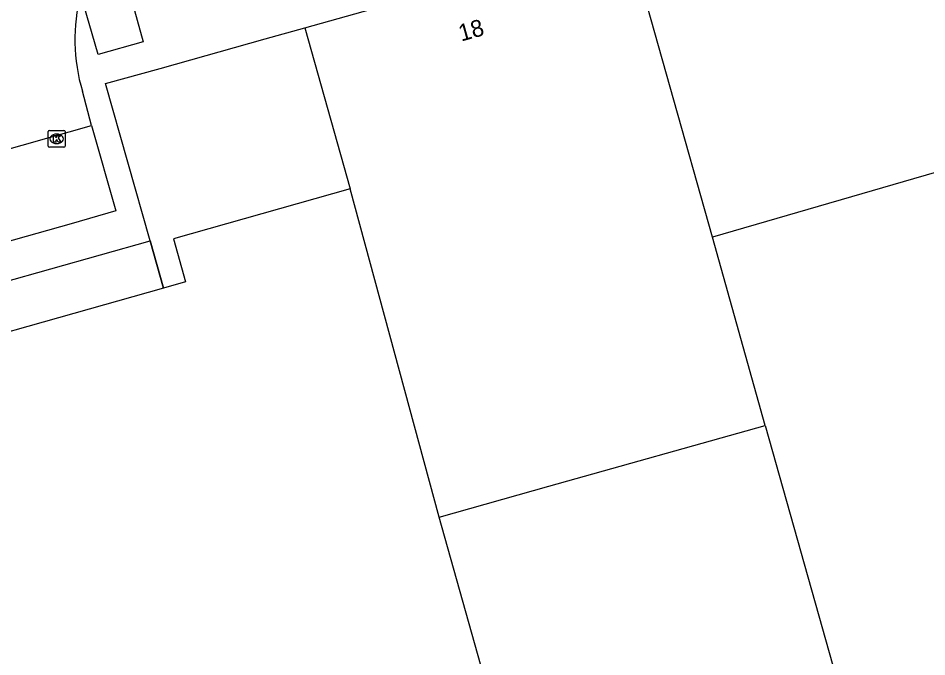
# Model space of a CAD drawing. Extents: x 159689 to 160786, y 387323 to 388339.
# Drawn here: x 159968.5 to 160022.4, y 388098.5 to 388136.4 of the extents above; entities that cross this region are included whole.
import ezdxf

# ---------------------------------------------------------------- set-up
doc = ezdxf.new("R2010")
doc.units = 0
for name, color, linetype in [('IMGEO_Hek', 7, 'Continuous'), ('IMGEO_Kolk', 7, 'Continuous'), ('IMGEO_Pand', 7, 'Continuous'), ('IMGEO_Pand_nummerreeks', 7, 'Continuous'), ('IMGEO_Rijbaan_lokaal_gesloten', 7, 'Continuous'), ('IMGEO_Voetpad_open', 7, 'Continuous')]:
    doc.layers.add(name, color=color, linetype=linetype)

msp = doc.modelspace()

# ---------------------------------------------------------------- linework, layer by layer
at = {"layer": 'IMGEO_Hek'}
msp.add_lwpolyline([(159976.338, 388123.222), (159977.127, 388120.422)], dxfattribs=at)
at = {"layer": 'IMGEO_Kolk'}
for p, q in [((159970.298, 388128.856), (159970.298, 388129.708)), ((159970.373, 388129.782), (159971.225, 388129.782)), ((159970.786, 388129.562), (159970.811, 388129.562)), ((159971.299, 388129.708), (159971.299, 388128.856)), ((159970.809, 388129.002), (159970.784, 388129.002)), ((159971.225, 388128.782), (159970.373, 388128.782))]:
    msp.add_line(p, q, dxfattribs=at)
for points in [[(159970.298, 388128.856), (159970.298, 388129.708)], [(159970.373, 388129.782), (159971.225, 388129.782)], [(159970.619, 388129.482), (159970.742, 388129.482), (159970.742, 388129.331), (159970.872, 388129.482), (159971.036, 388129.482), (159970.89, 388129.331), (159971.043, 388129.082), (159970.891, 388129.082), (159970.806, 388129.246), (159970.742, 388129.179), (159970.742, 388129.082), (159970.619, 388129.082), (159970.619, 388129.482)], [(159971.299, 388129.708), (159971.299, 388128.856)], [(159971.225, 388128.782), (159970.373, 388128.782)]]:
    msp.add_lwpolyline(points, dxfattribs=at)
for centre, start, end in [((159970.375, 388129.706), 91.552, 178.448), ((159970.375, 388129.706), 91.552, 178.448), ((159971.223, 388129.706), 1.552, 88.448), ((159971.223, 388129.706), 1.552, 88.448), ((159970.375, 388128.858), 181.552, 268.448), ((159970.375, 388128.858), 181.552, 268.448), ((159971.223, 388128.858), 271.552, 358.448), ((159971.223, 388128.858), 271.552, 358.448)]:
    msp.add_arc(centre, 0.0765, start, end, dxfattribs=at)
for centre, major_axis, ratio, start_param, end_param in [((159970.785, 388129.282), (-0.387, 0.002), 0.722429, 4.712389, 7.853982), ((159970.81, 388129.282), (-0.39, 0.002), 0.717154, 1.570796, 4.712389)]:
    msp.add_ellipse(centre, major_axis=major_axis, ratio=ratio, start_param=start_param, end_param=end_param, dxfattribs=at)
at = {"layer": 'IMGEO_Pand'}
for points in [[(159985.526, 388135.869), (160000, 388139.941), (160004.68, 388141.258)], [(160009.691, 388123.443), (160004.68, 388141.258)], [(159985.526, 388135.869), (159988.214, 388126.311)], [(160048.204, 388134.628), (160009.691, 388123.443)], [(159988.214, 388126.311), (159977.726, 388123.346), (159978.446, 388120.795), (159977.127, 388120.422)], [(159993.49, 388106.837), (159988.214, 388126.311)], [(160012.83, 388112.278), (160009.691, 388123.443)], [(159977.127, 388120.422), (159959.347, 388115.395), (159959.027, 388116.529), (159954.546, 388115.888), (159954.734, 388115.225), (159953.294, 388114.818), (159953.106, 388115.482), (159948.902, 388113.675), (159949.225, 388112.529), (159934.794, 388108.418)], [(159993.49, 388106.837), (160000, 388108.668), (160012.83, 388112.278)], [(160012.83, 388112.278), (160019.582, 388088.279)], [(160000.247, 388082.819), (160000, 388083.697), (159993.49, 388106.837)]]:
    msp.add_lwpolyline(points, dxfattribs=at)
at = {"layer": 'IMGEO_Rijbaan_lokaal_gesloten'}
for points in [[(159972.859, 388130.08), (159972.326, 388132.105)], [(159959.327, 388126.241), (159972.859, 388130.08)]]:
    msp.add_lwpolyline(points, dxfattribs=at)
msp.add_arc((159982.526, 388135.154), 10.646, 165.3966, 196.642, dxfattribs=at)
at = {"layer": 'IMGEO_Voetpad_open'}
for points in [[(159974.61, 388139.841), (159975.919, 388135.032), (159973.257, 388134.295), (159972.224, 388137.838)], [(159976.338, 388123.222), (159973.702, 388132.555), (159976.946, 388133.464), (159983.172, 388135.209), (159985.526, 388135.869)], [(159972.859, 388130.08), (159974.309, 388125), (159971.667, 388124.235), (159960.818, 388121.183)], [(159925.692, 388108.945), (159929.739, 388110.084), (159932.894, 388110.974), (159937.772, 388112.349), (159950.525, 388115.944), (159955.427, 388117.326), (159961.828, 388119.131), (159967.514, 388120.734), (159976.338, 388123.222)], [(159977.127, 388120.422), (159976.338, 388123.222)]]:
    msp.add_lwpolyline(points, dxfattribs=at)

# ---------------------------------------------------------------- texts
at = {"layer": 'IMGEO_Pand_nummerreeks'}
msp.add_text('18', height=1, rotation=15.713, dxfattribs=at).set_placement((159994.795, 388135.05))

doc.saveas('drawing.dxf')
